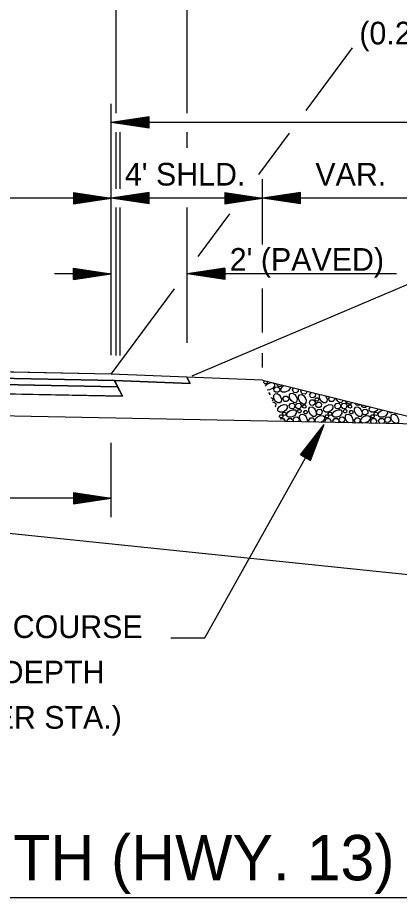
# Model space of a CAD drawing. Extents: x 2478 to 3210, y 439 to 841.
# Drawn here: x 2644.6 to 2664.77, y 562.28 to 608.84 of the extents above; entities that cross this region are included whole.
import ezdxf

# ---------------------------------------------------------------- set-up
doc = ezdxf.new("R2010")
doc.units = 0
for name, color, linetype in [('19', 7, 'Continuous'), ('R_Annotation', 7, 'Continuous'), ('R_Dimension', 7, 'Continuous'), ('R_Exist Surface', 7, 'Continuous')]:
    doc.layers.add(name, color=color, linetype=linetype)

msp = doc.modelspace()

# ---------------------------------------------------------------- linework, layer by layer
at = {"layer": '19'}
for points in [[(2601.503, 590.935), (2601.338, 590.605), (2605.378, 590.524), (2627.711, 590.078), (2649.713, 589.634), (2653.713, 589.474), (2653.543, 589.814), (2649.543, 589.974), (2627.543, 590.414)], [(2605.378, 590.524), (2605.212, 590.194), (2649.879, 589.301), (2649.713, 589.634)], [(2605.212, 590.194), (2604.965, 589.699), (2650.132, 588.796), (2649.879, 589.301)]]:
    msp.add_lwpolyline(points, close=True, dxfattribs=at)
at = {"layer": 'R_Annotation'}
for p, q in [((2649.543, 589.974), (2627.543, 590.414)), ((2649.713, 589.634), (2627.543, 590.081)), ((2657.543, 589.654), (2649.543, 589.974)), ((2649.879, 589.301), (2627.543, 589.748)), ((2649.713, 589.634), (2650.132, 588.796)), ((2653.713, 589.474), (2649.713, 589.634)), ((2653.543, 589.814), (2653.713, 589.474)), ((2657.543, 589.654), (2677.543, 584.654)), ((2650.132, 588.796), (2627.543, 589.247)), ((2666.995, 587.291), (2605.543, 588.52)), ((2580.788, 562.276), (2675.476, 562.276))]:
    msp.add_line(p, q, dxfattribs=at)
at = {"layer": 'R_Dimension'}
for p, q in [((2653.546, 603.781), (2653.546, 622.281)), ((2649.796, 603.781), (2649.796, 610.281)), ((2659.836, 603.915), (2662.286, 607.232)), ((2649.543, 599.281), (2649.543, 604.281)), ((2651.543, 603.581), (2649.543, 603.281)), ((2651.543, 603.531), (2649.877, 603.281)), ((2651.543, 603.48), (2650.221, 603.281)), ((2651.543, 602.981), (2651.543, 603.581)), ((2677.543, 603.281), (2649.543, 603.281)), ((2651.543, 602.981), (2649.543, 603.281)), ((2651.543, 603.031), (2649.877, 603.281)), ((2651.543, 603.082), (2650.221, 603.281)), ((2651.543, 603.43), (2650.554, 603.281)), ((2651.543, 603.132), (2650.554, 603.281)), ((2651.543, 603.379), (2650.893, 603.281)), ((2651.543, 603.184), (2650.893, 603.281)), ((2651.543, 603.328), (2651.227, 603.281)), ((2651.543, 603.234), (2651.227, 603.281)), ((2649.796, 599.781), (2649.796, 602.781)), ((2650.006, 599.781), (2650.006, 602.781)), ((2653.546, 601.952), (2653.546, 602.781)), ((2657.338, 600.532), (2658.958, 602.725)), ((2657.543, 596.837), (2657.543, 600.281)), ((2666.995, 599.281), (2586.003, 599.281)), ((2647.543, 599.581), (2649.543, 599.281)), ((2647.543, 599.581), (2647.543, 598.981)), ((2647.543, 599.531), (2649.209, 599.281)), ((2647.543, 599.48), (2648.865, 599.281)), ((2647.543, 599.43), (2648.532, 599.281)), ((2647.543, 599.378), (2648.193, 599.281)), ((2647.543, 599.328), (2647.859, 599.281)), ((2647.543, 598.981), (2649.543, 599.281)), ((2647.543, 599.183), (2648.193, 599.281)), ((2647.543, 599.082), (2648.865, 599.281)), ((2647.543, 599.031), (2649.209, 599.281)), ((2647.543, 599.132), (2648.532, 599.281)), ((2647.543, 599.234), (2647.859, 599.281)), ((2651.543, 599.581), (2649.543, 599.281)), ((2649.543, 590.975), (2649.543, 599.281)), ((2651.543, 598.981), (2649.543, 599.281)), ((2651.543, 599.531), (2649.877, 599.281)), ((2651.543, 599.031), (2649.877, 599.281)), ((2651.543, 599.48), (2650.221, 599.281)), ((2651.543, 599.082), (2650.221, 599.281)), ((2651.543, 599.43), (2650.554, 599.281)), ((2651.543, 599.132), (2650.554, 599.281)), ((2651.543, 599.379), (2650.893, 599.281)), ((2651.543, 599.184), (2650.893, 599.281)), ((2651.543, 599.328), (2651.227, 599.281)), ((2651.543, 599.234), (2651.227, 599.281)), ((2651.543, 598.981), (2651.543, 599.581)), ((2655.543, 599.581), (2657.543, 599.281)), ((2655.543, 599.581), (2655.543, 598.981)), ((2655.543, 599.531), (2657.209, 599.281)), ((2655.543, 599.48), (2656.865, 599.281)), ((2655.543, 599.43), (2656.532, 599.281)), ((2655.543, 599.378), (2656.193, 599.281)), ((2655.543, 599.328), (2655.859, 599.281)), ((2655.543, 598.981), (2657.543, 599.281)), ((2655.543, 599.183), (2656.193, 599.281)), ((2655.543, 599.082), (2656.865, 599.281)), ((2655.543, 599.031), (2657.209, 599.281)), ((2655.543, 599.132), (2656.532, 599.281)), ((2655.543, 599.234), (2655.859, 599.281)), ((2659.543, 599.581), (2657.543, 599.281)), ((2659.543, 598.981), (2657.543, 599.281)), ((2659.543, 599.531), (2657.877, 599.281)), ((2659.543, 599.031), (2657.877, 599.281)), ((2659.543, 599.48), (2658.221, 599.281)), ((2659.543, 599.082), (2658.221, 599.281)), ((2659.543, 599.43), (2658.554, 599.281)), ((2659.543, 599.132), (2658.554, 599.281)), ((2659.543, 599.379), (2658.893, 599.281)), ((2659.543, 599.184), (2658.893, 599.281)), ((2659.543, 599.328), (2659.227, 599.281)), ((2659.543, 599.234), (2659.227, 599.281)), ((2659.543, 598.981), (2659.543, 599.581)), ((2649.796, 590.963), (2649.796, 598.781)), ((2650.006, 590.963), (2650.006, 598.781)), ((2653.546, 591.629), (2653.546, 598.781)), ((2654.138, 596.197), (2655.804, 598.454)), ((2647.543, 595.581), (2649.543, 595.281)), ((2647.543, 594.981), (2647.543, 595.581)), ((2655.546, 595.581), (2653.546, 595.281)), ((2653.822, 589.875), (2667.759, 595.805)), ((2655.546, 595.581), (2655.546, 594.981)), ((2649.543, 595.281), (2646.543, 595.281)), ((2647.543, 595.531), (2649.209, 595.281)), ((2647.543, 595.48), (2648.865, 595.281)), ((2647.543, 595.43), (2648.532, 595.281)), ((2647.543, 595.379), (2648.193, 595.281)), ((2647.543, 595.328), (2647.859, 595.281)), ((2647.543, 594.981), (2649.543, 595.281)), ((2647.543, 595.184), (2648.193, 595.281)), ((2647.543, 595.082), (2648.865, 595.281)), ((2647.543, 595.031), (2649.209, 595.281)), ((2647.543, 595.132), (2648.532, 595.281)), ((2647.543, 595.234), (2647.859, 595.281)), ((2655.546, 594.981), (2653.546, 595.281)), ((2664.623, 595.281), (2653.546, 595.281)), ((2655.546, 595.531), (2653.88, 595.281)), ((2655.546, 595.031), (2653.88, 595.281)), ((2655.546, 595.48), (2654.224, 595.281)), ((2655.546, 595.082), (2654.224, 595.281)), ((2655.546, 595.43), (2654.557, 595.281)), ((2655.546, 595.132), (2654.557, 595.281)), ((2655.546, 595.378), (2654.896, 595.281)), ((2655.546, 595.183), (2654.896, 595.281)), ((2655.546, 595.328), (2655.23, 595.281)), ((2655.546, 595.234), (2655.23, 595.281)), ((2649.543, 589.974), (2652.878, 594.491)), ((2657.543, 592.17), (2657.543, 594.503)), ((2657.543, 590.315), (2657.543, 591.073)), ((2657.612, 589.503), (2657.603, 589.559)), ((2658.638, 589.344), (2658.693, 589.367)), ((2659.128, 589.154), (2659.189, 589.243)), ((2659.568, 589.079), (2659.611, 589.137)), ((2660.87, 588.822), (2660.893, 588.794)), ((2661.033, 588.684), (2661.09, 588.767)), ((2658.442, 587.695), (2658.428, 587.754)), ((2663.788, 588.024), (2663.895, 588.066)), ((2658.855, 587.454), (2658.843, 587.504)), ((2659.551, 585.697), (2660.789, 587.296)), ((2660.075, 585.404), (2660.789, 587.296)), ((2660.859, 587.414), (2660.838, 587.489)), ((2661.282, 587.405), (2661.258, 587.504)), ((2659.595, 585.673), (2660.626, 587.005)), ((2660.031, 585.429), (2660.626, 587.005)), ((2649.543, 582.406), (2649.543, 586.336)), ((2659.639, 585.648), (2660.458, 586.705)), ((2659.683, 585.624), (2660.296, 586.414)), ((2659.943, 585.478), (2660.296, 586.414)), ((2659.987, 585.454), (2660.458, 586.705)), ((2659.728, 585.598), (2660.13, 586.118)), ((2659.772, 585.574), (2659.967, 585.827)), ((2659.854, 585.528), (2659.967, 585.827)), ((2659.899, 585.503), (2660.13, 586.118)), ((2659.551, 585.697), (2660.075, 585.404)), ((2647.543, 583.706), (2649.543, 583.406)), ((2647.543, 583.706), (2647.543, 583.106)), ((2647.543, 583.656), (2649.209, 583.406)), ((2647.543, 583.605), (2648.865, 583.406)), ((2647.543, 583.555), (2648.532, 583.406)), ((2647.543, 583.503), (2648.193, 583.406)), ((2647.543, 583.453), (2647.859, 583.406)), ((2649.543, 583.406), (2605.543, 583.406)), ((2647.543, 583.106), (2649.543, 583.406)), ((2647.543, 583.308), (2648.193, 583.406)), ((2647.543, 583.207), (2648.865, 583.406)), ((2647.543, 583.156), (2649.209, 583.406)), ((2647.543, 583.257), (2648.532, 583.406)), ((2647.543, 583.359), (2647.859, 583.406))]:
    msp.add_line(p, q, dxfattribs=at)
for points in [[(2657.603, 589.559), (2657.653, 589.624), (2657.66, 589.625)], [(2657.756, 589.601), (2657.783, 589.574), (2657.773, 589.499), (2657.728, 589.454), (2657.653, 589.459), (2657.615, 589.497)], [(2657.808, 589.464), (2657.963, 589.524), (2658.103, 589.514), (2658.168, 589.454), (2658.168, 589.339), (2658.063, 589.214), (2657.908, 589.134), (2657.783, 589.13)], [(2657.691, 589.331), (2657.738, 589.409), (2657.818, 589.469)], [(2658.138, 589.174), (2658.223, 589.289), (2658.348, 589.294), (2658.443, 589.204), (2658.428, 589.074), (2658.343, 589.009), (2658.218, 589.019), (2658.158, 589.074), (2658.138, 589.174)], [(2658.579, 589.395), (2658.578, 589.384), (2658.503, 589.314), (2658.373, 589.324), (2658.318, 589.384), (2658.29, 589.468)], [(2658.996, 589.291), (2658.993, 589.214), (2658.888, 589.084), (2658.738, 589.009), (2658.588, 589.009), (2658.508, 589.064), (2658.503, 589.179), (2658.568, 589.284), (2658.643, 589.344)], [(2659.423, 589.184), (2659.428, 589.179), (2659.418, 589.049), (2659.338, 588.979), (2659.208, 588.994), (2659.148, 589.054), (2659.128, 589.154)], [(2659.87, 589.073), (2659.863, 588.979), (2659.783, 588.914), (2659.653, 588.919), (2659.593, 588.979), (2659.568, 589.079)], [(2657.845, 588.995), (2657.918, 588.914), (2657.913, 588.849)], [(2657.971, 588.721), (2658.023, 588.724), (2658.078, 588.669), (2658.073, 588.589), (2658.044, 588.563)], [(2658.468, 588.799), (2658.533, 588.649), (2658.518, 588.509), (2658.453, 588.444), (2658.343, 588.449), (2658.213, 588.544), (2658.138, 588.699), (2658.133, 588.849), (2658.198, 588.934), (2658.308, 588.939), (2658.418, 588.869), (2658.478, 588.794)], [(2658.618, 588.684), (2658.698, 588.799), (2658.828, 588.809), (2658.923, 588.719), (2658.903, 588.589), (2658.828, 588.524), (2658.698, 588.529), (2658.638, 588.589), (2658.618, 588.684)], [(2659.303, 588.824), (2659.363, 588.669), (2659.348, 588.529), (2659.283, 588.459), (2659.168, 588.469), (2659.043, 588.569), (2658.958, 588.724), (2658.958, 588.869), (2659.018, 588.954), (2659.138, 588.959), (2659.238, 588.894), (2659.303, 588.814)], [(2659.778, 588.749), (2659.838, 588.594), (2659.828, 588.454), (2659.768, 588.389), (2659.653, 588.394), (2659.528, 588.494), (2659.443, 588.649), (2659.443, 588.794), (2659.498, 588.874), (2659.613, 588.889), (2659.723, 588.814), (2659.783, 588.739)], [(2660.013, 588.484), (2660.093, 588.604), (2660.218, 588.609), (2660.313, 588.509), (2660.303, 588.384), (2660.213, 588.314), (2660.088, 588.319), (2660.028, 588.384), (2660.013, 588.484)], [(2660.033, 588.889), (2660.108, 588.999), (2660.15, 589.002)], [(2660.284, 588.969), (2660.333, 588.914), (2660.323, 588.784), (2660.238, 588.719), (2660.108, 588.729), (2660.048, 588.784), (2660.033, 588.889)], [(2660.313, 588.649), (2660.358, 588.719), (2660.438, 588.724), (2660.493, 588.669), (2660.488, 588.589), (2660.438, 588.544), (2660.358, 588.554), (2660.323, 588.589), (2660.313, 588.649)], [(2660.883, 588.799), (2660.948, 588.649), (2660.933, 588.509), (2660.868, 588.444), (2660.758, 588.449), (2660.628, 588.544), (2660.553, 588.699), (2660.548, 588.849), (2660.582, 588.894)], [(2661.336, 588.706), (2661.318, 588.589), (2661.243, 588.524), (2661.113, 588.529), (2661.053, 588.589), (2661.033, 588.684)], [(2661.77, 588.598), (2661.763, 588.529), (2661.698, 588.459), (2661.583, 588.469), (2661.458, 588.569), (2661.39, 588.692)], [(2658.078, 588.489), (2658.153, 588.494), (2658.238, 588.394), (2658.223, 588.264), (2658.193, 588.239)], [(2658.493, 588.299), (2658.643, 588.359), (2658.778, 588.349), (2658.843, 588.289), (2658.843, 588.174), (2658.748, 588.044), (2658.588, 587.964), (2658.443, 587.964), (2658.353, 588.019), (2658.348, 588.134), (2658.418, 588.244), (2658.498, 588.304)], [(2658.943, 588.309), (2659.018, 588.424), (2659.153, 588.429), (2659.248, 588.339), (2659.233, 588.204), (2659.148, 588.139), (2659.018, 588.149), (2658.958, 588.204), (2658.943, 588.309)], [(2659.273, 588.304), (2659.363, 588.419), (2659.488, 588.429), (2659.583, 588.334), (2659.563, 588.199), (2659.488, 588.134), (2659.358, 588.144), (2659.303, 588.204), (2659.273, 588.304)], [(2659.648, 588.264), (2659.703, 588.339), (2659.773, 588.339), (2659.828, 588.289), (2659.823, 588.204), (2659.773, 588.174), (2659.693, 588.179), (2659.658, 588.204), (2659.648, 588.264)], [(2660.318, 588.089), (2660.378, 587.944), (2660.368, 587.804), (2660.308, 587.734), (2660.193, 587.734), (2660.068, 587.839), (2659.983, 587.994), (2659.983, 588.139), (2660.038, 588.229), (2660.158, 588.234), (2660.263, 588.169), (2660.323, 588.084)], [(2660.353, 588.364), (2660.433, 588.484), (2660.568, 588.494), (2660.653, 588.394), (2660.638, 588.264), (2660.563, 588.199), (2660.433, 588.204), (2660.373, 588.264), (2660.353, 588.364)], [(2660.393, 587.989), (2660.468, 588.104), (2660.598, 588.114), (2660.693, 588.014), (2660.678, 587.884), (2660.593, 587.819), (2660.468, 587.824), (2660.408, 587.884), (2660.393, 587.989)], [(2660.908, 588.299), (2661.058, 588.359), (2661.193, 588.349), (2661.258, 588.289), (2661.258, 588.174), (2661.163, 588.044), (2661.003, 587.964), (2660.858, 587.964), (2660.768, 588.019), (2660.763, 588.134), (2660.833, 588.244), (2660.913, 588.304)], [(2661.358, 588.309), (2661.433, 588.424), (2661.568, 588.429), (2661.663, 588.339), (2661.648, 588.204), (2661.563, 588.139), (2661.433, 588.149), (2661.373, 588.204), (2661.358, 588.309)], [(2661.688, 588.304), (2661.778, 588.419), (2661.903, 588.429), (2661.998, 588.334), (2661.978, 588.199), (2661.903, 588.134), (2661.773, 588.144), (2661.718, 588.204), (2661.688, 588.304)], [(2662.244, 588.479), (2662.243, 588.454), (2662.183, 588.389), (2662.068, 588.394), (2661.943, 588.494), (2661.904, 588.564)], [(2662.063, 588.264), (2662.118, 588.339), (2662.188, 588.339), (2662.243, 588.289), (2662.238, 588.204), (2662.188, 588.174), (2662.108, 588.179), (2662.073, 588.204), (2662.063, 588.264)], [(2662.733, 588.089), (2662.793, 587.944), (2662.783, 587.804), (2662.723, 587.734), (2662.608, 587.734), (2662.483, 587.839), (2662.398, 587.994), (2662.398, 588.139), (2662.453, 588.229), (2662.573, 588.234), (2662.678, 588.169), (2662.738, 588.084)], [(2662.694, 588.366), (2662.628, 588.314), (2662.503, 588.319), (2662.443, 588.384), (2662.436, 588.431)], [(2663.054, 588.277), (2663.053, 588.264), (2662.978, 588.199), (2662.848, 588.204), (2662.788, 588.264), (2662.771, 588.347)], [(2662.808, 587.989), (2662.883, 588.104), (2663.013, 588.114), (2663.108, 588.014), (2663.093, 587.884), (2663.008, 587.819), (2662.883, 587.824), (2662.823, 587.884), (2662.808, 587.989)], [(2663.64, 588.13), (2663.578, 588.044), (2663.418, 587.964), (2663.273, 587.964), (2663.183, 588.019), (2663.178, 588.134), (2663.239, 588.23)], [(2658.428, 587.754), (2658.478, 587.819), (2658.558, 587.824), (2658.613, 587.769), (2658.603, 587.689), (2658.558, 587.649), (2658.478, 587.654), (2658.443, 587.694)], [(2658.598, 587.894), (2658.648, 587.959), (2658.723, 587.964), (2658.778, 587.909), (2658.773, 587.834), (2658.723, 587.789), (2658.648, 587.799), (2658.613, 587.834), (2658.598, 587.894)], [(2658.958, 588.024), (2659.113, 588.084), (2659.253, 588.074), (2659.318, 588.014), (2659.318, 587.899), (2659.218, 587.769), (2659.058, 587.694), (2658.908, 587.689), (2658.828, 587.749), (2658.823, 587.869), (2658.888, 587.969), (2658.968, 588.029)], [(2659.163, 587.584), (2659.238, 587.699), (2659.373, 587.709), (2659.468, 587.614), (2659.448, 587.484), (2659.397, 587.443)], [(2659.393, 588.024), (2659.443, 588.094), (2659.528, 588.094), (2659.583, 588.044), (2659.563, 587.964), (2659.518, 587.924), (2659.443, 587.929), (2659.413, 587.964), (2659.393, 588.024)], [(2659.608, 587.439), (2659.583, 587.459), (2659.503, 587.604), (2659.498, 587.759), (2659.558, 587.839), (2659.673, 587.849), (2659.783, 587.784), (2659.848, 587.704)], [(2659.718, 587.964), (2659.768, 588.039), (2659.848, 588.044), (2659.898, 587.989), (2659.888, 587.904), (2659.838, 587.869), (2659.768, 587.874), (2659.728, 587.904), (2659.718, 587.964)], [(2659.838, 587.709), (2659.898, 587.564), (2659.889, 587.433)], [(2659.978, 587.539), (2660.063, 587.654), (2660.193, 587.659), (2660.273, 587.569), (2660.263, 587.439), (2660.248, 587.426)], [(2660.338, 587.424), (2660.318, 587.439), (2660.313, 587.554), (2660.378, 587.659), (2660.453, 587.724)], [(2660.443, 587.714), (2660.593, 587.774), (2660.738, 587.764), (2660.808, 587.704), (2660.803, 587.589), (2660.698, 587.464), (2660.612, 587.419)], [(2660.843, 587.754), (2660.893, 587.819), (2660.973, 587.824), (2661.028, 587.769), (2661.018, 587.689), (2660.973, 587.649), (2660.893, 587.654), (2660.858, 587.694), (2660.843, 587.754)], [(2661.013, 587.894), (2661.063, 587.959), (2661.138, 587.964), (2661.193, 587.909), (2661.188, 587.834), (2661.138, 587.789), (2661.063, 587.799), (2661.028, 587.834), (2661.013, 587.894)], [(2661.373, 588.024), (2661.528, 588.084), (2661.668, 588.074), (2661.733, 588.014), (2661.733, 587.899), (2661.633, 587.769), (2661.473, 587.694), (2661.323, 587.689), (2661.243, 587.749), (2661.238, 587.869), (2661.303, 587.969), (2661.383, 588.029)], [(2661.578, 587.584), (2661.653, 587.699), (2661.788, 587.709), (2661.883, 587.614), (2661.863, 587.484), (2661.783, 587.419), (2661.653, 587.424), (2661.593, 587.484), (2661.578, 587.584)], [(2661.808, 588.024), (2661.858, 588.094), (2661.943, 588.094), (2661.998, 588.044), (2661.978, 587.964), (2661.933, 587.924), (2661.858, 587.929), (2661.828, 587.964), (2661.808, 588.024)], [(2662.084, 587.389), (2661.998, 587.459), (2661.918, 587.604), (2661.913, 587.759), (2661.973, 587.839), (2662.088, 587.849), (2662.198, 587.784), (2662.263, 587.704)], [(2662.133, 587.964), (2662.183, 588.039), (2662.263, 588.044), (2662.313, 587.989), (2662.303, 587.904), (2662.253, 587.869), (2662.183, 587.874), (2662.143, 587.904), (2662.133, 587.964)], [(2662.253, 587.709), (2662.313, 587.564), (2662.303, 587.419), (2662.271, 587.386)], [(2662.393, 587.539), (2662.478, 587.654), (2662.608, 587.659), (2662.688, 587.569), (2662.678, 587.439), (2662.613, 587.379)], [(2662.858, 587.714), (2663.008, 587.774), (2663.153, 587.764), (2663.223, 587.704), (2663.218, 587.589), (2663.113, 587.464), (2662.963, 587.384), (2662.813, 587.379), (2662.733, 587.439), (2662.728, 587.554), (2662.793, 587.659), (2662.868, 587.724)], [(2663.258, 587.754), (2663.308, 587.819), (2663.388, 587.824), (2663.443, 587.769), (2663.433, 587.689), (2663.388, 587.649), (2663.308, 587.654), (2663.273, 587.694), (2663.258, 587.754)], [(2663.428, 587.894), (2663.478, 587.959), (2663.553, 587.964), (2663.608, 587.909), (2663.603, 587.834), (2663.553, 587.789), (2663.478, 587.799), (2663.443, 587.834), (2663.428, 587.894)], [(2664.148, 588.003), (2664.148, 587.899), (2664.048, 587.769), (2663.888, 587.694), (2663.738, 587.689), (2663.658, 587.749), (2663.653, 587.869), (2663.718, 587.969), (2663.798, 588.029)], [(2663.993, 587.584), (2664.068, 587.699), (2664.203, 587.709), (2664.298, 587.614), (2664.278, 587.484), (2664.198, 587.419), (2664.068, 587.424), (2664.008, 587.484), (2663.993, 587.584)], [(2664.373, 587.947), (2664.348, 587.924), (2664.273, 587.929), (2664.243, 587.964), (2664.237, 587.981)], [(2664.668, 587.709), (2664.728, 587.564), (2664.718, 587.419), (2664.658, 587.354), (2664.543, 587.354), (2664.413, 587.459), (2664.333, 587.604), (2664.328, 587.759), (2664.388, 587.839), (2664.503, 587.849), (2664.613, 587.784), (2664.678, 587.704)], [(2664.672, 587.872), (2664.668, 587.869), (2664.598, 587.874), (2664.565, 587.899)], [(2652.686, 576.022), (2654.484, 576.022), (2660.789, 587.296)], [(2658.49, 587.592), (2658.508, 587.614), (2658.638, 587.624), (2658.723, 587.524), (2658.717, 587.457)], [(2658.843, 587.504), (2658.928, 587.614), (2659.058, 587.629), (2659.148, 587.529), (2659.135, 587.448)], [(2659.215, 587.447), (2659.178, 587.484), (2659.163, 587.584)], [(2660.002, 587.431), (2659.993, 587.439), (2659.978, 587.539)], [(2660.838, 587.504), (2660.923, 587.614), (2661.053, 587.624), (2661.138, 587.524), (2661.128, 587.409)], [(2661.258, 587.504), (2661.343, 587.614), (2661.473, 587.629), (2661.563, 587.529), (2661.543, 587.4)], [(2662.475, 587.382), (2662.408, 587.439), (2662.393, 587.539)], [(2663.253, 587.504), (2663.338, 587.614), (2663.468, 587.624), (2663.553, 587.524), (2663.543, 587.399), (2663.502, 587.361)], [(2663.309, 587.365), (2663.278, 587.399), (2663.253, 587.489)], [(2663.673, 587.504), (2663.758, 587.614), (2663.888, 587.629), (2663.978, 587.529), (2663.958, 587.399), (2663.904, 587.353)], [(2663.746, 587.356), (2663.698, 587.404), (2663.673, 587.504)]]:
    msp.add_lwpolyline(points, dxfattribs=at)
at = {"layer": 'R_Exist Surface'}
msp.add_lwpolyline([(2559.048, 580.013), (2580.798, 583.038), (2610.269, 580.01), (2642.749, 581.692), (2680.214, 577.819), (2705.082, 582.167)], dxfattribs=at)

# ---------------------------------------------------------------- texts
at = {"layer": 'R_Annotation'}
for s, height, p in [("(0.22' BELOW PROFILE GRADE).", 1.2, (2662.652, 607.42)), ("4' SHLD.", 1.2, (2650.261, 599.951)), ('VAR.', 1.2, (2660.328, 599.951)), ("2' (PAVED)", 1.2, (2655.803, 595.442)), ('AGGREGATE BASE COURSE', 1.2, (2629, 576.003)), ("(CLASS 7) - VAR. COMP'D. DEPTH", 1.2, (2623.293, 573.603)), ('(VAR. TONS PER STA.)', 1.2, (2632.628, 571.203)), ('SUPERELEVATION SECTION - FULL DEPTH (HWY. 13)', 2.4, (2581.943, 563.179))]:
    msp.add_text(s, height=height, dxfattribs=at).set_placement(p)

doc.saveas('drawing.dxf')
